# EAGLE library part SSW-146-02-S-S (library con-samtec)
THROUGH-HOLE .025" SQ POST SOCKET Source: Samtec SSW.pdf
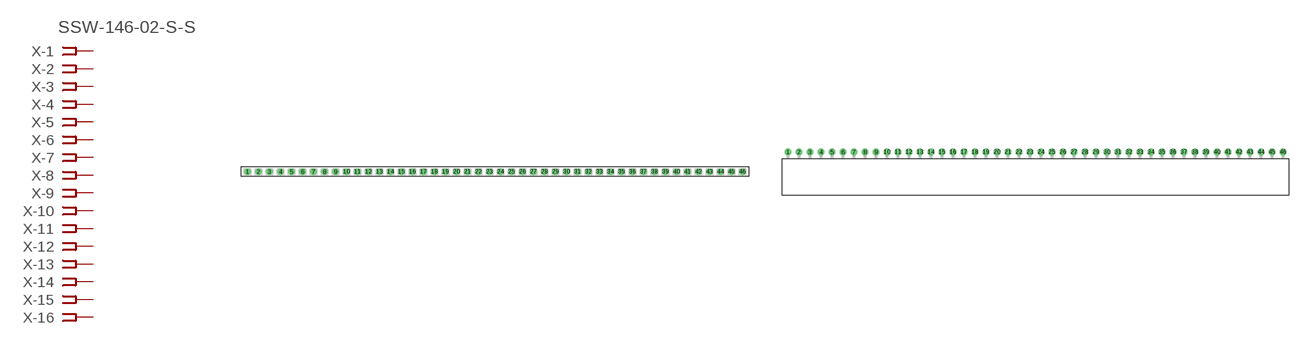
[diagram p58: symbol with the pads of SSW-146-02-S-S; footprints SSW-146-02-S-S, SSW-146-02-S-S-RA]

Designator prefix X; gates -1=FPINV -2=FPIN -3=FPIN -4=FPIN -5=FPIN -6=FPIN -7=FPIN -8=FPIN -9=FPIN -10=FPIN -11=FPIN -12=FPIN -13=FPIN -14=FPIN -15=FPIN -16=FPIN -17=FPIN -18=FPIN -19=FPIN -20=FPIN -21=FPIN -22=FPIN -23=FPIN -24=FPIN -25=FPIN -26=FPIN -27=FPIN -28=FPIN -29=FPIN -30=FPIN -31=FPIN -32=FPIN -33=FPIN -34=FPIN -35=FPIN -36=FPIN -37=FPIN -38=FPIN -39=FPIN -40=FPIN -41=FPIN -42=FPIN -43=FPIN -44=FPIN -45=FPIN -46=FPIN

## SSW-146-02-S-S (MPN: SSW-146-02-S-S; OC_FARNELL: unknown; OC_NEWARK: 12P0025)  [SSW-146-02-S-S]
1  -1:1  pas
2  -2:1  pas
3  -3:1  pas
4  -4:1  pas
5  -5:1  pas
6  -6:1  pas
7  -7:1  pas
8  -8:1  pas
9  -9:1  pas
10  -10:1  pas
11  -11:1  pas
12  -12:1  pas
13  -13:1  pas
14  -14:1  pas
15  -15:1  pas
16  -16:1  pas
17  -17:1  pas
18  -18:1  pas
19  -19:1  pas
20  -20:1  pas
21  -21:1  pas
22  -22:1  pas
23  -23:1  pas
24  -24:1  pas
25  -25:1  pas
26  -26:1  pas
27  -27:1  pas
28  -28:1  pas
29  -29:1  pas
30  -30:1  pas
31  -31:1  pas
32  -32:1  pas
33  -33:1  pas
34  -34:1  pas
35  -35:1  pas
36  -36:1  pas
37  -37:1  pas
38  -38:1  pas
39  -39:1  pas
40  -40:1  pas
41  -41:1  pas
42  -42:1  pas
43  -43:1  pas
44  -44:1  pas
45  -45:1  pas
46  -46:1  pas

## SSW-146-02-S-S-RA (MPN: SSW-146-02-S-S-RA; OC_FARNELL: unknown; OC_NEWARK: 12P0026)  [SSW-146-02-S-S-RA]
Pads as for SSW-146-02-S-S

## Footprint SSW-146-02-S-S (pad centres in mm)
THROUGH-HOLE .025" SQ POST SOCKET Source: Samtec SSW.pdf
drill 1 pad 1.5 octagon: 1 -57.15,0; 2 -54.61,0; 3 -52.07,0; 4 -49.53,0; 5 -46.99,0; 6 -44.45,0; 7 -41.91,0; 8 -39.37,0; 9 -36.83,0; 10 -34.29,0; 11 -31.75,0; 12 -29.21,0; 13 -26.67,0; 14 -24.13,0; 15 -21.59,0; 16 -19.05,0; 17 -16.51,0; 18 -13.97,0; 19 -11.43,0; 20 -8.89,0; 21 -6.35,0; 22 -3.81,0; 23 -1.27,0; 24 1.27,0; 25 3.81,0; 26 6.35,0; 27 8.89,0; 28 11.43,0; 29 13.97,0; 30 16.51,0; 31 19.05,0; 32 21.59,0; 33 24.13,0; 34 26.67,0; 35 29.21,0; 36 31.75,0; 37 34.29,0; 38 36.83,0; 39 39.37,0; 40 41.91,0; 41 44.45,0; 42 46.99,0; 43 49.53,0; 44 52.07,0; 45 54.61,0; 46 57.15,0

## Footprint SSW-146-02-S-S-RA (pad centres in mm)
THROUGH-HOLE .025" SQ POST SOCKET Source: Samtec SSW.pdf
drill 1 pad 1.5 octagon: 1 -57.15,1.524; 2 -54.61,1.524; 3 -52.07,1.524; 4 -49.53,1.524; 5 -46.99,1.524; 6 -44.45,1.524; 7 -41.91,1.524; 8 -39.37,1.524; 9 -36.83,1.524; 10 -34.29,1.524; 11 -31.75,1.524; 12 -29.21,1.524; 13 -26.67,1.524; 14 -24.13,1.524; 15 -21.59,1.524; 16 -19.05,1.524; 17 -16.51,1.524; 18 -13.97,1.524; 19 -11.43,1.524; 20 -8.89,1.524; 21 -6.35,1.524; 22 -3.81,1.524; 23 -1.27,1.524; 24 1.27,1.524; 25 3.81,1.524; 26 6.35,1.524; 27 8.89,1.524; 28 11.43,1.524; 29 13.97,1.524; 30 16.51,1.524; 31 19.05,1.524; 32 21.59,1.524; 33 24.13,1.524; 34 26.67,1.524; 35 29.21,1.524; 36 31.75,1.524; 37 34.29,1.524; 38 36.83,1.524; 39 39.37,1.524; 40 41.91,1.524; 41 44.45,1.524; 42 46.99,1.524; 43 49.53,1.524; 44 52.07,1.524; 45 54.61,1.524; 46 57.15,1.524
